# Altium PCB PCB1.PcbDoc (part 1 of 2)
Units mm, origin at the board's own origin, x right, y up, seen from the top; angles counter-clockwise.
Board outline 98.6 x 67.31 mm, 4 copper layers (Top Layer, GND, PWR, Bottom Layer), stack 1.57 mm thick; 89 components, 101 nets, 372 pads, 350 vias.
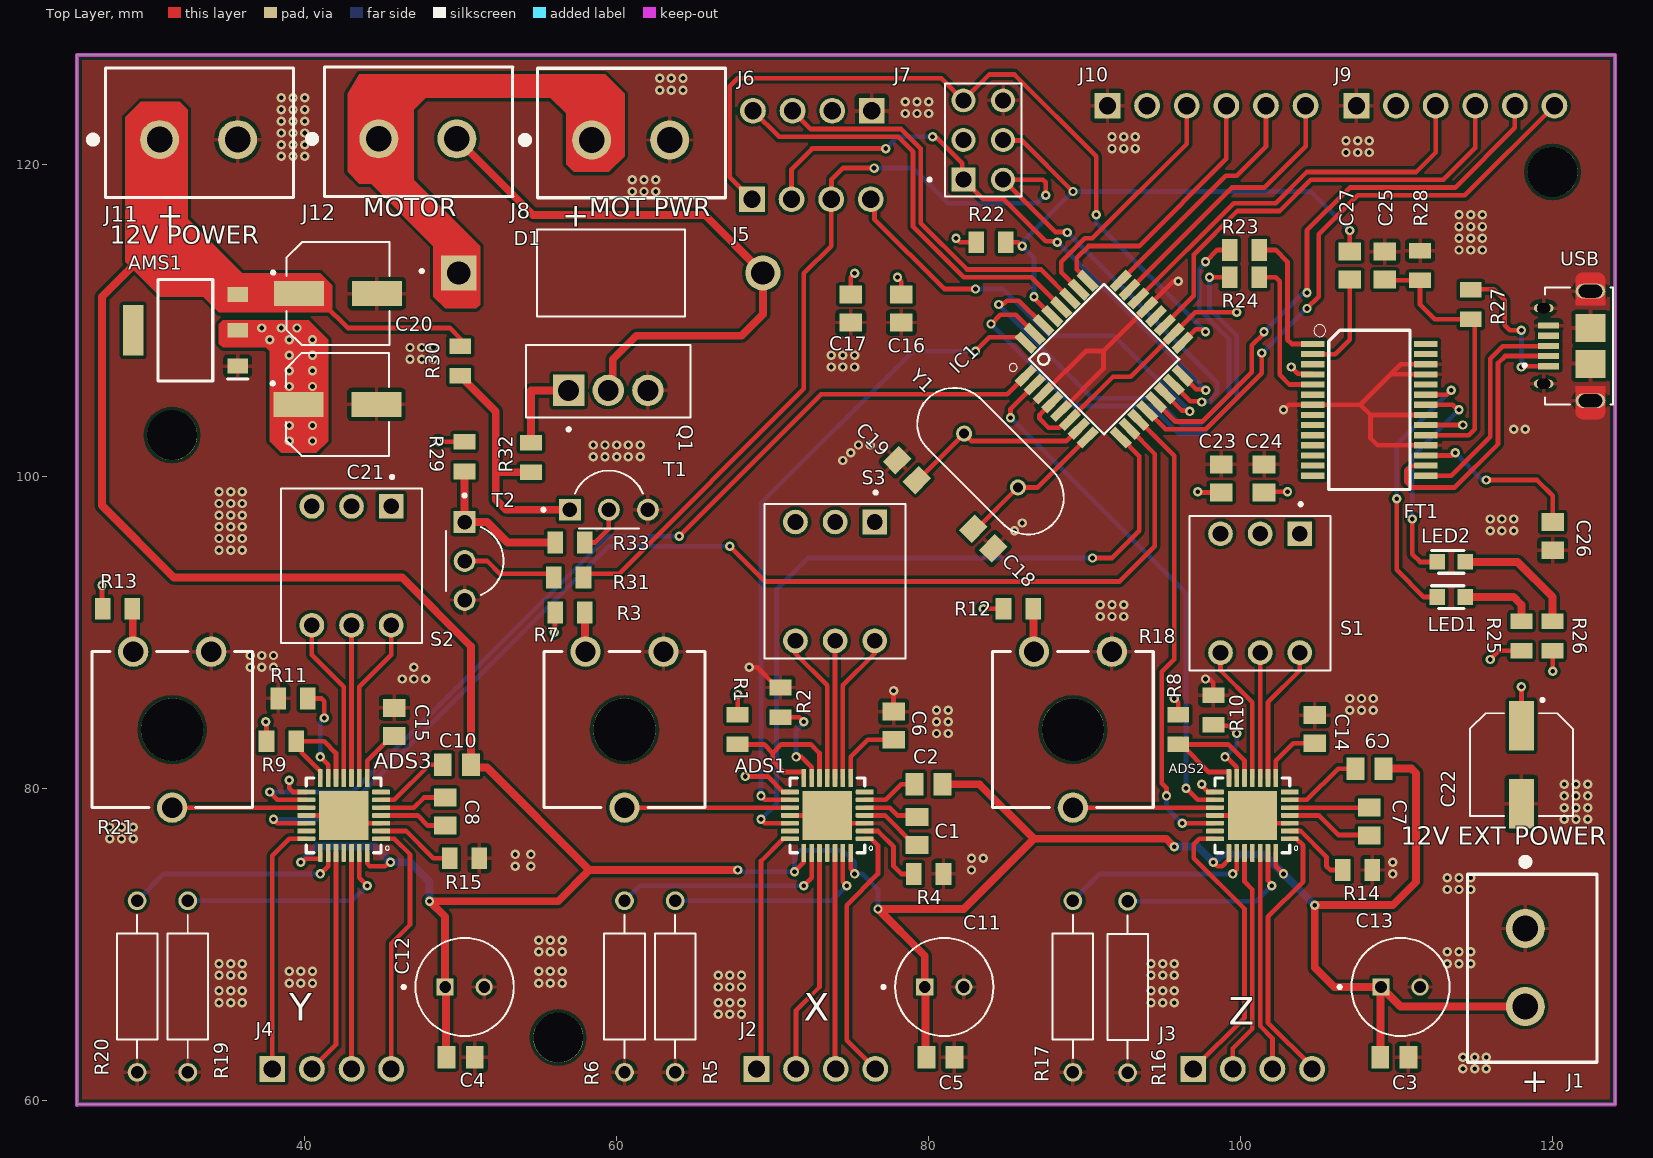
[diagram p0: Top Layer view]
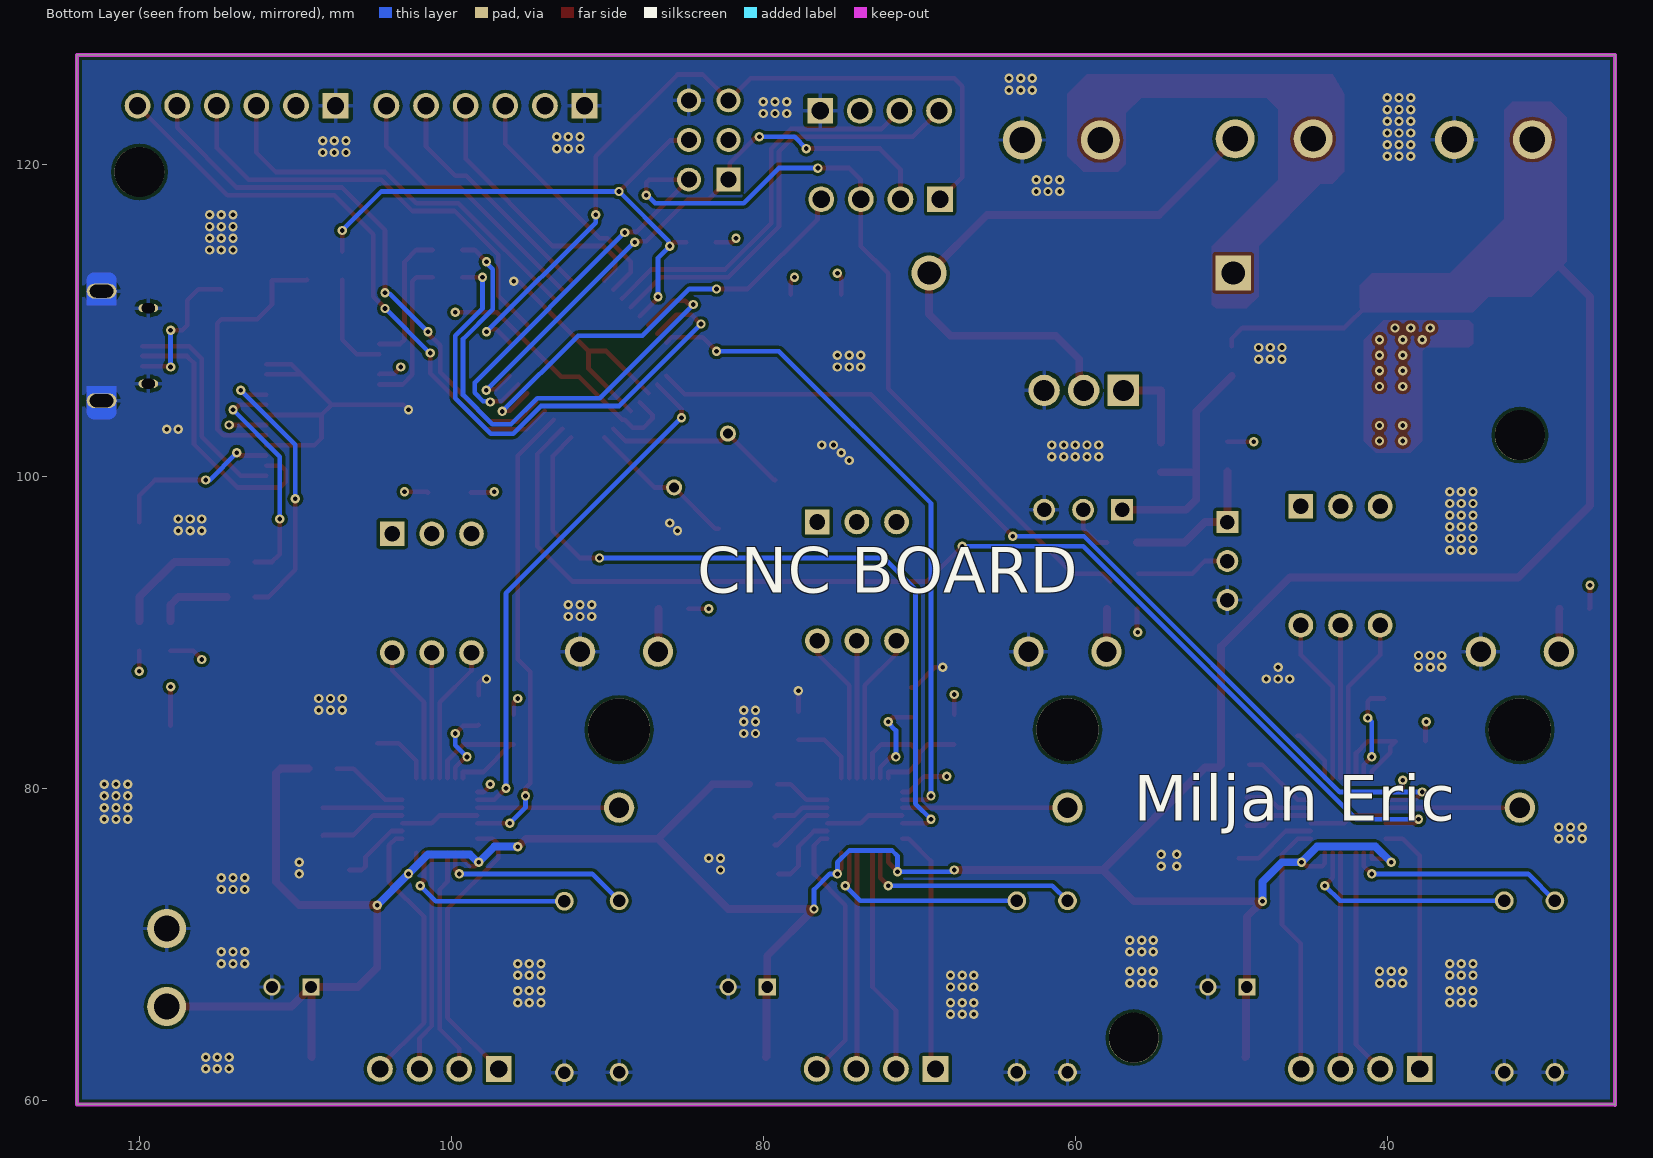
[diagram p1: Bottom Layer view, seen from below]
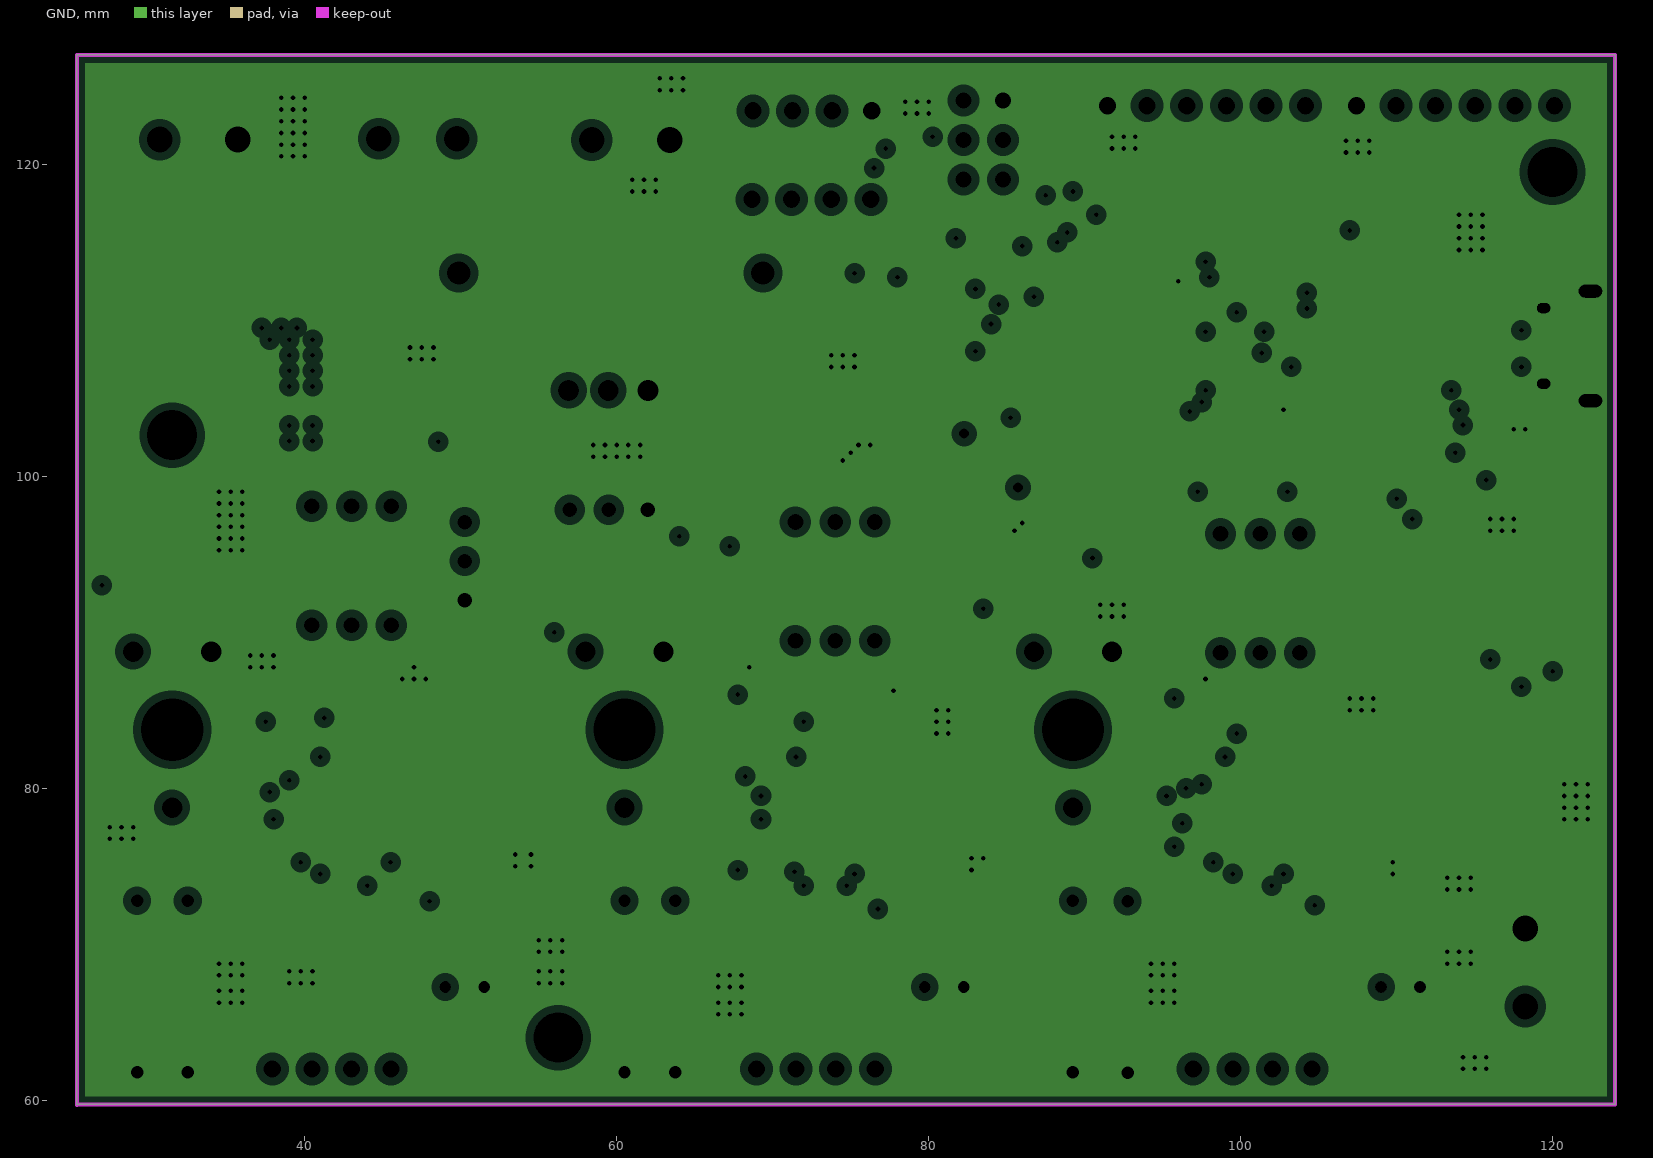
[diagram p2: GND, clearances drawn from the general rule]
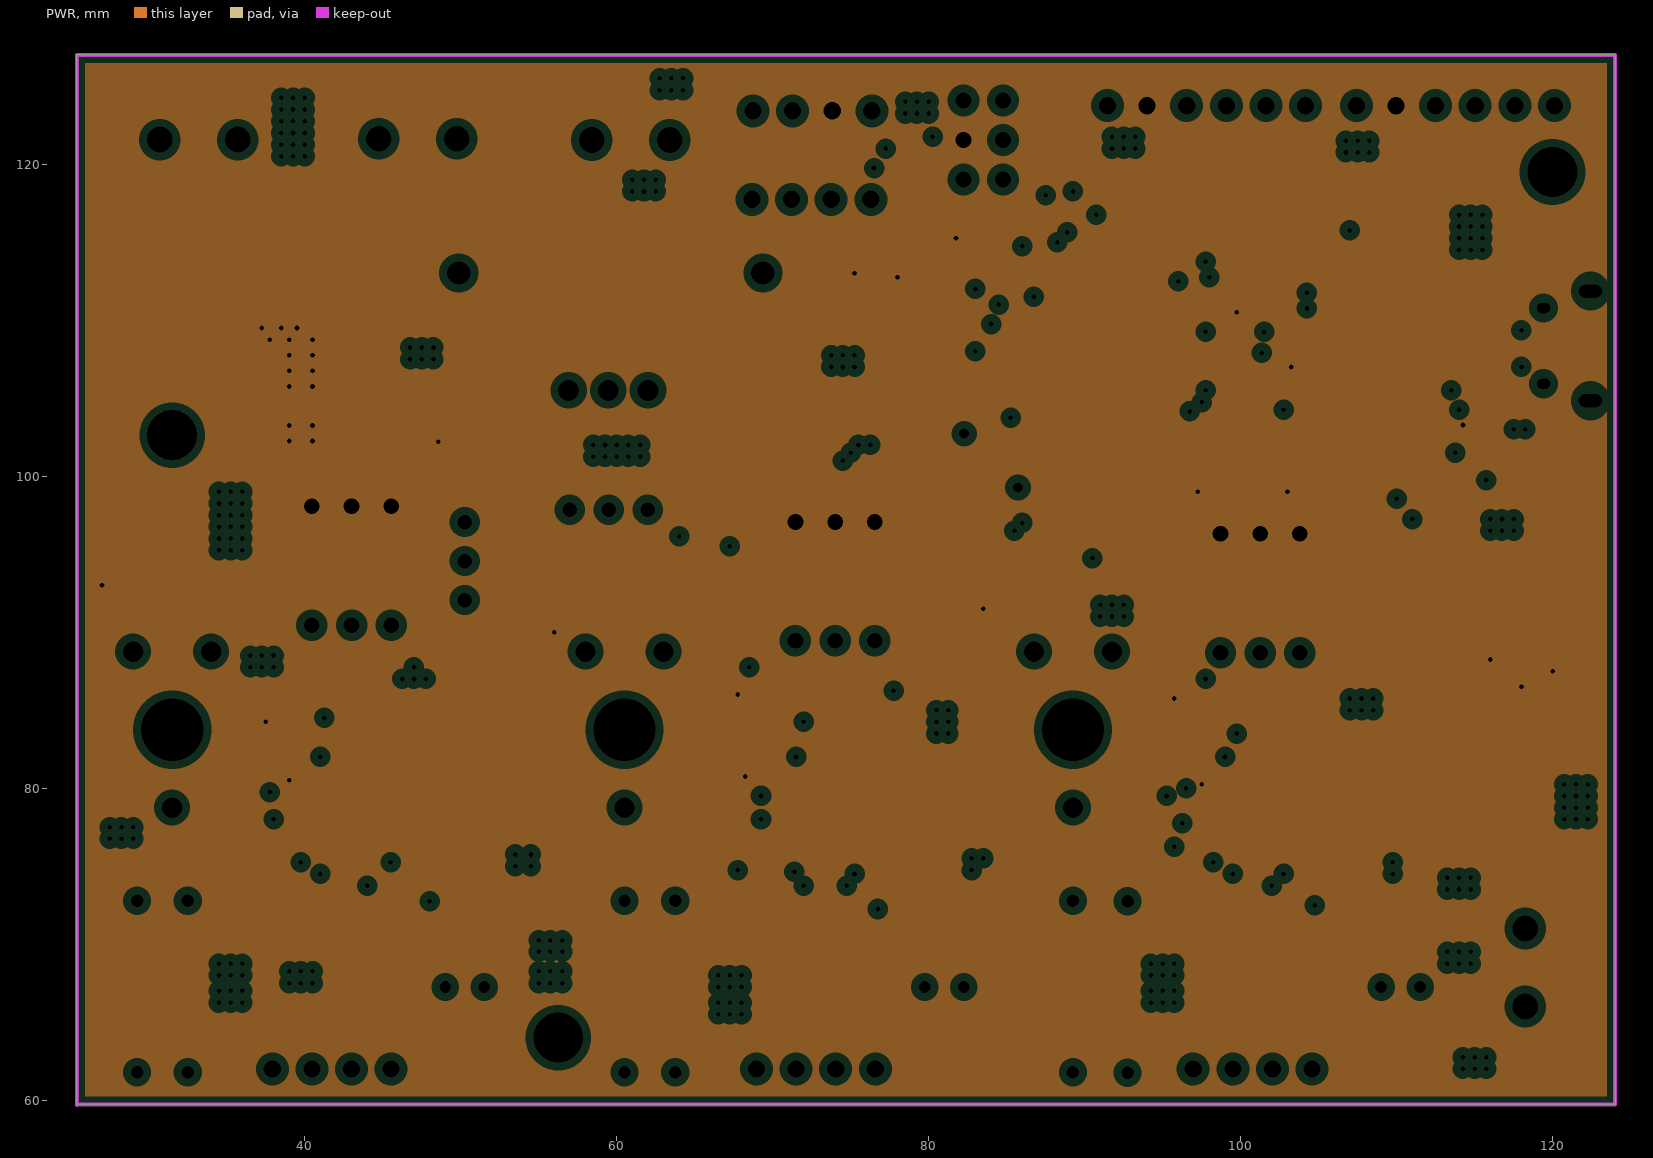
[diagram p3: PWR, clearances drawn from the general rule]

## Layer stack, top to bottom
Top Solder: solder mask 0.0102, Solder Resist, Dk 3.5
Top Layer: signal copper 0.035
Dielectric 2: prepreg 0.2, PP-006, Dk 4.1
GND: plane copper 0.0175, net GND
Dielectric 1: dielectric 1.065, FR-4, Dk 4.8
PWR: plane copper 0.0175, net VCC_5V
Dielectric 3: prepreg 0.2, PP-006, Dk 4.1
Bottom Layer: signal copper 0.035
Bottom Solder: solder mask 0.0102, Solder Resist, Dk 3.5

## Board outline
25.4,59.69 25.431,59.721 124,59.721 124,127 25.4,127

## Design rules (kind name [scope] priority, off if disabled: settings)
Clearance [All] p1: gap=0.2 ignorepadtopadclearanceinfootprint=FALSE
HoleSize [All] p1: absolutevalues=TRUE maxlimit=4 minlimit=0.025 maxpercent=80.000 minpercent=20.000
MinimumSolderMaskSliver [All] p1: minsoldermaskwidth=0.046
PlaneClearance [All] p1: clearance=0.508
PlaneConnect [All] p1: pad.planeconnectstyle=Relief pad.reliefexpansion=0.508 pad.reliefentries=4 pad.reliefconductorwidth=0.254 pad.reliefairgap=0.254 via.planeconnectstyle=Direct via.reliefexpansion=0.508 via.reliefentries=4 via.reliefconductorwidth=0.254 via.reliefairgap=0.254
PolygonConnect [All] p1: thpad.connectstyle=Relief thpad.reliefconductorwidth=0.254 thpad.reliefentries=4 thpad.polygonreliefangle="90 Angle" thpad.airgapwidth=0.254 smdpad.connectstyle=Relief smdpad.reliefconductorwidth=0.254 smdpad.reliefentries=4 smdpad.polygonreliefangle="90 Angle" smdpad.airgapwidth=0.254 via.connectstyle=Direct via.reliefconductorwidth=0.254 via.reliefentries=4 via.polygonreliefangle="90 Angle" via.airgapwidth=0.254
RoutingVias [All] p1: holewidth=0.711 width=1.27 viastyle="Through Hole" minholewidth=0.711 minwidth=1.27 maxholewidth=0.711 maxwidth=1.27
SilkToSilkClearance [All] p1: silktosilkclearance=0.001
SilkToSolderMaskClearance [IsPad] p1: minsilkscreentomaskgap=0.001 clearancetoexposedcopper=TRUE
SolderMaskExpansion [All] p1: expansion=0.102
UnpouredPolygon [All] p1: allowunpoured=TRUE allowshelved=TRUE
Width [All] p1: maxlimit=0.5 minlimit=0.2 preferedwidth=0.3
23 further rules are at their usual default settings.

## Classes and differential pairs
component class U_A4988Driver: ADS1 ADS2 ADS3 C1 C2 C3 C4 C5 C6 C7 C8 C9 C10 C11 C12 C13 C14 C15 J1 J2 J3 J4 R1 R2 R3 R4 R5 R6 R7 R8 R9 R10 R11 R12 R13 R14 R15 R16 R17 R18 R19 R20 R21 S1 S2 S3
component class U_ATMega328-AU: C16 C17 C18 C19 IC1 J5 J6 J7 J8 J9 J10 R22 R23 R24 Y1
component class U_FT232RL: C22 C23 C24 C25 C26 C27 FT1 LED1 LED2 R25 R26 R27 R28 USB
component class U_IRF540MotorControl: D1 J12 Q1 R29 R30 R31 R32 R33 T1 T2
component class U_PowerSchematics: AMS1 C20 C21 J11

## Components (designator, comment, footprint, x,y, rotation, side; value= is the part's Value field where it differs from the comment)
ADS1 "A4982" QFN50P500X500X90-29N 73.5,78.25 r180 top
ADS2 "A4982" QFN50P500X500X90-29N 100.75,78.25 r180 top
ADS3 "A4982" QFN50P500X500X90-29N 42.5,78.25 r180 top
AMS1 "AMS1117-5.0" SOT229P700X180-4N 32.35,109.35 r180 top
C1 "0.1uF" CAPC2012X140N 79.25,77.25 r270 top
C2 "0.1uF" CAPC2012X140N 80,80.25 r0 top
C3 "4.7uF" CAPC2012X140N 109.85,62.75 r180 top
C4 "0.1uF" CAPC2012X140N 50,62.75 r180 top
C5 "0.1uF" CAPC2012X140N 80.75,62.75 r180 top
C6 "0.22uF" CAPC2012X140N 77.75,84 r270 top
C7 "0.1uF" CAPC2012X140N 108.25,77.85 r270 top
C8 "0.1uF" CAPC2012X140N 49,78.5 r270 top
C9 "0.1uF" CAPC2012X140N 108.25,81.25 r0 top
C10 "0.1uF" CAPC2012X140N 49.75,81.5 r0 top
C11 "Cap Pol1" CAPPRD250W50D630H1500 81,67.25 r0 top value=100uF
C12 "Cap Pol1" CAPPRD250W50D630H1500 50.25,67.25 r0 top value=100uF
C13 "Cap Pol1" CAPPRD250W50D630H1500 110.25,67.25 r0 top value=100uF
C14 "0.22uF" CAPC2012X140N 104.75,83.775 r270 top
C15 "0.22uF" CAPC2012X140N 45.75,84.25 r270 top
C16 "100nF" CAPC2012X140N 78.25,110.75 r90 top
C17 "100nF" CAPC2012X140N 75,110.75 r90 top
C18 "22pF" CAPC2012X140N 83.5,96 r315 top
C19 "22pF" CAPC2012X140N 78.614,100.386 r135 top
C20 "10uF" CAP_EEE1CA101WAP 42.125,111.7 r0 top
C21 "10uF" CAP_EEE1CA101WAP 42.1,104.6 r0 top
C22 "10uF" CAP_EEE1CA101WAP 118,81.5 r270 top
C23 "100nF" CAPC2012X140N 98.75,99.85 r270 top
C24 "10nF" CAPC2012X140N 101.5,99.85 r270 top
C25 "100nF" CAPC2012X140N 109.25,113.5 r270 top
C26 "100nF" CAPC2012X140N 120,96.15 r90 top
C27 "100nF" CAPC2012X140N 107,113.5 r90 top
D1 "B550C-13-F" DIOAD1950W125L950D560 59.625,113.025 r0 top
FT1 "FT232RL" SSOP28-0.65-10.2X5.2MM 108.25,104.25 r270 top
IC1 "ATMEGA328-AU" QFP80P900X900X120-32N 91.25,107.5 r45 top
J1 "DB2EVC-3.5-2P-GN" 5MM_2POS_TERM_BLOCK 118.25,71 r270 top
J2 "2.54mm" HEADER1X4 68.96,62 r0 top
J3 "2.54mm" HEADER1X4 96.96,62 r0 top
J4 "2.54mm" HEADER1X4 37.92,62 r0 top
J5 "2.54mm" HEADER1X4 68.67,117.75 r0 top
J6 "2.54mm" HEADER1X4 76.355,123.425 r180 top
J7 "2.54mm" TE_5-146257-3 83.5,121.55 r90 top
J8 "DB2EVC-3.5-2P-GN" 5MM_2POS_TERM_BLOCK 58.4,121.55 r0 top
J9 "2.54mm" HEADER1X6 107.42,123.75 r0 top
J10 "2.54mm" HEADER1X6 91.464,123.75 r0 top
J11 "DB2EVC-3.5-2P-GN" 5MM_2POS_TERM_BLOCK 30.7,121.575 r0 top
J12 "DB2EVC-3.5-2P-GN" 5MM_2POS_TERM_BLOCK 44.75,121.625 r0 top
LED1 "LED-RED" LEDM168X65N_RED 113.5,92.25 r0 top
LED2 "LED-GREEN" LEDM168X65N_GREEN 113.5,94.5 r0 top
Q1 "IRF540NSTRLPBF" TO254P1052X465X1989-3 56.92,105.5 r0 top
R1 "100K" RESC2012X60N 67.75,83.75 r90 top
R2 "10K" RESC2012X60N 70.5,85.5 r270 top
R3 "10K" RESC2012X60N 57,91.25 r180 top
R4 "100K" RESC2012X60N 80,74.5 r180 top
R5 "0.1R" RESAD1100W55L680D260 63.75,67.278 r90 top
R6 "0.1R" RESAD1100W55L680D260 60.5,67.278 r90 top
R7 "RPot" PT10RV10103A2020PMS 63,88.75 r180 top value=5K
R8 "100K" RESC2012X60N 96,83.75 r90 top
R9 "100K" RESC2012X60N 38.5,83 r180 top
R10 "10K" RESC2012X60N 98.25,85 r270 top
R11 "10K" RESC2012X60N 39.25,85.75 r0 top
R12 "10K" RESC2012X60N 85.75,91.5 r180 top
R13 "10K" RESC2012X60N 28,91.5 r180 top
R14 "100K" RESC2012X60N 107.5,74.75 r180 top
R15 "100K" RESC2012X60N 50.25,75.5 r180 top
R16 "0.1R" RESAD1100W55L680D260 92.75,67.25 r90 top
R17 "0.1R" RESAD1100W55L680D260 89.25,67.278 r90 top
R18 "RPot" PT10RV10103A2020PMS 91.75,88.75 r180 top value=5K
R19 "0.1R" RESAD1100W55L680D260 32.5,67.278 r90 top
R20 "0.1R" RESAD1100W55L680D260 29.25,67.278 r90 top
R21 "RPot" PT10RV10103A2020PMS 34,88.75 r180 top value=5K
R22 "10K" RESC2012X60N 84,115 r180 top
R23 "1K" RESC2012X60N 100.25,114.5 r0 top
R24 "1K" RESC2012X60N 100.25,112.75 r0 top
R25 "330R" RESC2012X60N 118,89.75 r270 top
R26 "330R" RESC2012X60N 120,89.75 r270 top
R27 "4K7" RESC2012X60N 114.75,111 r90 top
R28 "10K" RESC2012X60N 111.5,113.5 r270 top
R29 "4K7" RESC2012X60N 50.25,101.25 r90 top
R30 "10K" RESC2012X60N 49.975,107.375 r90 top
R31 "470R" RESC2012X60N 56.92,93.5 r180 top
R32 "470R" RESC2012X60N 54.5,101.2 r90 top
R33 "470R" RESC2012X60N 57,95.75 r0 top
S1 "DS04-254-2-03BK-SMT" SW_DS01-254-S-03BE 101.25,92.5 r180 top
S2 "DS04-254-2-03BK-SMT" SW_DS01-254-S-03BE 43,94.25 r180 top
S3 "DS04-254-2-03BK-SMT" SW_DS01-254-S-03BE 74,93.25 r180 top
T1 "BC547" TO92250P510H770-3 59.5,98.5 r0 top
T2 "BC547" TO92250P510H770-3 50.905,94.56 r270 top
USB "ZX62D-B-5P8" HRS_ZX62D-B-5P8 122.35,108.35 r90 top
Y1 "ABL-16.000MHZ" XTAL_ECS-30-S-1X 84,101 r315 top

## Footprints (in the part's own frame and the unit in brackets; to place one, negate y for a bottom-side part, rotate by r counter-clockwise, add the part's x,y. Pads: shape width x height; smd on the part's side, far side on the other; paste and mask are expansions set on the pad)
5MM_2POS_TERM_BLOCK [mm]
  round 2.5 hole 1.65: 1(0,0) 2(5,0)
  silkscreen extent -4.47,-3.7 8.58,4.6, body extent -2.54,-2.9 7.62,4.35, height 9.68
CAP_EEE1CA101WAP [mm]
  rect 3.2x1.6 smd: 1(-2.5,0) 2(2.5,0)
  silkscreen extent -4.25,-3.3 3.3,3.3, body extent -3.65,-3.3 3.65,3.3, height 5.8
CAPC2012X140N [mm]
  rect 1.15x1.45 smd: 1(-0.9,0) 2(0.9,0)
  body extent -1,-0.63 1,0.63, height 0.94
CAPPRD250W50D630H1500 [mm]
  rect 1.1x1.1 / inner round 1.1 / far side rect 1.1x1.1 hole 0.75: 1(-1.25,0)
  round 1.1 hole 0.75: 2(1.25,0)
  silkscreen extent -4,-3.15 3.15,3.15, body extent -3.15,-3.15 3.15,3.15, height 15
DIOAD1950W125L950D560 [mm]
  rect 2.25x2.25 hole 1.5: 1(-9.75,0)
  round 2.25 hole 1.5: 2(9.75,0)
  silkscreen extent -12.22,-2.8 4.75,2.8, body extent -10.38,-2.65 10.78,2.65, height 5.3
HEADER1X4 [mm]
  rect 1.65x1.65 hole 1.1: 1(0,0)
  round 1.65 hole 1.1: 2(2.54,0) 3(5.08,0) 4(7.62,0)
  body extent -1.27,-1.27 8.89,1.27, height 8.7
HEADER1X6 [mm]
  rect 1.65x1.65 hole 1.1: 1(0,0)
  round 1.65 hole 1.1: 2(2.54,0) 3(5.08,0) 4(7.62,0) 5(10.16,0) 6(12.7,0)
  body extent -1.19,-1.22 13.89,1.22, height 8.7
HRS_ZX62D-B-5P8 [mm]
  rect 0.4x1.35 smd mask+0.1: 1(-1.3,2.6) 2(-0.65,2.6) 3(0,2.6) 4(0.65,2.6) 5(1.3,2.6)
  oval 0.525x1.25 hole 0.65 slot 0.85 at 90 deg mask+0.1: S1(-2.425,2.925) S2(2.425,2.925)
  oval 0.95x1.9 hole 0.825 slot 1.5 at 90 deg mask+0.1: S3(-3.512,-0.075) S6(3.512,-0.075)
  rect 1.8x1.9 smd mask+0.1: S4(-1.15,-0.075) S5(1.15,-0.075)
  Top Layer region: 4.226,0.874 4.252,0.872 4.278,0.869 4.304,0.864 4.329,0.858 4.355,0.851 4.379,0.842 4.403,0.832 4.427,0.821 4.45,0.808 4.472,0.794 4.494,0.78 4.515,0.764 4.535,0.747 4.554,0.729 4.572,0.71 4.589,0.69 4.605,0.669 4.619,0.647 4.633,0.625 4.646,0.602 4.657,0.578 4.667,0.554 4.676,0.53 4.683,0.504 4.689,0.479 4.694,0.453 4.697,0.427 4.699,0.401 4.7,0.375 4.7,-0.075 3.925,-0.075 3.925,0.4 3.925,0.414 3.923,0.429 3.922,0.443 3.919,0.457 3.916,0.471 3.912,0.485 3.907,0.499 3.901,0.512 3.895,0.525 3.888,0.538 3.881,0.55 3.872,0.562 3.864,0.573 3.854,0.584 3.844,0.594 3.834,0.604 3.823,0.614 3.812,0.622 3.8,0.631 3.787,0.638 3.775,0.645 3.762,0.651 3.749,0.657 3.735,0.662 3.721,0.666 3.707,0.669 3.693,0.672 3.679,0.673 3.664,0.675 3.384,0.675 3.369,0.673 3.353,0.671 3.338,0.668 3.322,0.665 3.307,0.66 3.292,0.655 3.278,0.649 3.264,0.642 3.25,0.635 3.237,0.627 3.224,0.618 3.211,0.608 3.199,0.598 3.188,0.587 3.177,0.576 3.167,0.564 3.157,0.551 3.148,0.538 3.14,0.525 3.133,0.511 3.126,0.497 3.12,0.483 3.115,0.468 3.11,0.453 3.107,0.437 3.104,0.422 3.102,0.406 3.1,0.391 3.1,0.375 3.1,-0.075 2.6,-0.075 2.6,0.875 4.2,0.875
  Top Layer region: -2.6,-1.025 -4.2,-1.025 -4.226,-1.024 -4.252,-1.022 -4.278,-1.019 -4.304,-1.014 -4.329,-1.008 -4.355,-1.001 -4.379,-0.992 -4.403,-0.982 -4.427,-0.971 -4.45,-0.958 -4.472,-0.944 -4.494,-0.93 -4.515,-0.914 -4.535,-0.897 -4.554,-0.879 -4.572,-0.86 -4.589,-0.84 -4.605,-0.819 -4.619,-0.797 -4.633,-0.775 -4.646,-0.752 -4.657,-0.728 -4.667,-0.704 -4.676,-0.68 -4.683,-0.654 -4.689,-0.629 -4.694,-0.603 -4.697,-0.577 -4.699,-0.551 -4.7,-0.525 -4.7,-0.075 -3.925,-0.075 -3.925,-0.55 -3.925,-0.564 -3.923,-0.579 -3.922,-0.593 -3.919,-0.607 -3.916,-0.621 -3.912,-0.635 -3.907,-0.649 -3.901,-0.662 -3.895,-0.675 -3.888,-0.688 -3.881,-0.7 -3.872,-0.712 -3.864,-0.723 -3.854,-0.734 -3.844,-0.744 -3.834,-0.754 -3.823,-0.764 -3.812,-0.772 -3.8,-0.781 -3.787,-0.788 -3.775,-0.795 -3.762,-0.801 -3.749,-0.807 -3.735,-0.812 -3.721,-0.816 -3.707,-0.819 -3.693,-0.822 -3.679,-0.823 -3.664,-0.825 -3.384,-0.825 -3.369,-0.823 -3.353,-0.821 -3.338,-0.818 -3.322,-0.815 -3.307,-0.81 -3.292,-0.805 -3.278,-0.799 -3.264,-0.792 -3.25,-0.785 -3.237,-0.777 -3.224,-0.768 -3.211,-0.758 -3.199,-0.748 -3.188,-0.737 -3.177,-0.726 -3.167,-0.714 -3.157,-0.701 -3.148,-0.688 -3.14,-0.675 -3.133,-0.661 -3.126,-0.647 -3.12,-0.633 -3.115,-0.618 -3.11,-0.603 -3.107,-0.587 -3.104,-0.572 -3.102,-0.556 -3.1,-0.541 -3.1,-0.525 -3.1,-0.075 -2.6,-0.075
  Top Layer region: 4.7,-0.525 4.699,-0.551 4.697,-0.577 4.694,-0.603 4.689,-0.629 4.683,-0.654 4.676,-0.68 4.667,-0.704 4.657,-0.728 4.646,-0.752 4.633,-0.775 4.619,-0.797 4.605,-0.819 4.589,-0.84 4.572,-0.86 4.554,-0.879 4.535,-0.897 4.515,-0.914 4.494,-0.93 4.472,-0.944 4.45,-0.958 4.427,-0.971 4.403,-0.982 4.379,-0.992 4.355,-1.001 4.329,-1.008 4.304,-1.014 4.278,-1.019 4.252,-1.022 4.226,-1.024 4.2,-1.025 2.6,-1.025 2.6,-0.075 3.1,-0.075 3.1,-0.525 3.1,-0.541 3.102,-0.556 3.104,-0.572 3.107,-0.587 3.11,-0.603 3.115,-0.618 3.12,-0.633 3.126,-0.647 3.133,-0.661 3.14,-0.675 3.148,-0.688 3.157,-0.701 3.167,-0.714 3.177,-0.726 3.188,-0.737 3.199,-0.748 3.211,-0.758 3.224,-0.768 3.237,-0.777 3.25,-0.785 3.264,-0.792 3.278,-0.799 3.292,-0.805 3.307,-0.81 3.322,-0.815 3.338,-0.818 3.353,-0.821 3.369,-0.823 3.384,-0.825 3.641,-0.825 3.656,-0.823 3.672,-0.821 3.687,-0.818 3.703,-0.815 3.718,-0.81 3.733,-0.805 3.747,-0.799 3.761,-0.792 3.775,-0.785 3.788,-0.777 3.801,-0.768 3.814,-0.758 3.826,-0.748 3.837,-0.737 3.848,-0.726 3.858,-0.714 3.868,-0.701 3.877,-0.688 3.885,-0.675 3.892,-0.661 3.899,-0.647 3.905,-0.633 3.91,-0.618 3.915,-0.603 3.918,-0.587 3.921,-0.572 3.923,-0.556 3.925,-0.541 3.925,-0.525 3.925,-0.075 4.7,-0.075
  Top Layer region: -2.6,-0.075 -3.1,-0.075 -3.1,0.375 -3.1,0.391 -3.102,0.406 -3.104,0.422 -3.107,0.437 -3.11,0.453 -3.115,0.468 -3.12,0.483 -3.126,0.497 -3.133,0.511 -3.14,0.525 -3.148,0.538 -3.157,0.551 -3.167,0.564 -3.177,0.576 -3.188,0.587 -3.199,0.598 -3.211,0.608 -3.224,0.618 -3.237,0.627 -3.25,0.635 -3.264,0.642 -3.278,0.649 -3.292,0.655 -3.307,0.66 -3.322,0.665 -3.338,0.668 -3.353,0.671 -3.369,0.673 -3.384,0.675 -3.641,0.675 -3.656,0.673 -3.672,0.671 -3.687,0.668 -3.703,0.665 -3.718,0.66 -3.733,0.655 -3.747,0.649 -3.761,0.642 -3.775,0.635 -3.788,0.627 -3.801,0.618 -3.814,0.608 -3.826,0.598 -3.837,0.587 -3.848,0.576 -3.858,0.564 -3.868,0.551 -3.877,0.538 -3.885,0.525 -3.892,0.511 -3.899,0.497 -3.905,0.483 -3.91,0.468 -3.915,0.453 -3.918,0.437 -3.921,0.422 -3.923,0.406 -3.925,0.391 -3.925,0.375 -3.925,-0.075 -4.7,-0.075 -4.7,0.375 -4.699,0.401 -4.697,0.427 -4.694,0.453 -4.689,0.479 -4.683,0.504 -4.676,0.53 -4.667,0.554 -4.657,0.578 -4.646,0.602 -4.633,0.625 -4.619,0.647 -4.605,0.669 -4.589,0.69 -4.572,0.71 -4.554,0.729 -4.535,0.747 -4.515,0.764 -4.494,0.78 -4.472,0.794 -4.45,0.808 -4.427,0.821 -4.403,0.832 -4.379,0.842 -4.355,0.851 -4.329,0.858 -4.304,0.864 -4.278,0.869 -4.252,0.872 -4.226,0.874 -4.2,0.875 -2.6,0.875
  Bottom Layer region: 4.226,0.874 4.252,0.872 4.278,0.869 4.304,0.864 4.329,0.858 4.355,0.851 4.379,0.842 4.403,0.832 4.427,0.821 4.45,0.808 4.472,0.794 4.494,0.78 4.515,0.764 4.535,0.747 4.554,0.729 4.572,0.71 4.589,0.69 4.605,0.669 4.619,0.647 4.633,0.625 4.646,0.602 4.657,0.578 4.667,0.554 4.676,0.53 4.683,0.504 4.689,0.479 4.694,0.453 4.697,0.427 4.699,0.401 4.7,0.375 4.7,-0.075 3.925,-0.075 3.925,0.4 3.925,0.414 3.923,0.429 3.922,0.443 3.919,0.457 3.916,0.471 3.912,0.485 3.907,0.499 3.901,0.512 3.895,0.525 3.888,0.538 3.881,0.55 3.872,0.562 3.864,0.573 3.854,0.584 3.844,0.594 3.834,0.604 3.823,0.614 3.812,0.622 3.8,0.631 3.787,0.638 3.775,0.645 3.762,0.651 3.749,0.657 3.735,0.662 3.721,0.666 3.707,0.669 3.693,0.672 3.679,0.673 3.664,0.675 3.384,0.675 3.369,0.673 3.353,0.671 3.338,0.668 3.322,0.665 3.307,0.66 3.292,0.655 3.278,0.649 3.264,0.642 3.25,0.635 3.237,0.627 3.224,0.618 3.211,0.608 3.199,0.598 3.188,0.587 3.177,0.576 3.167,0.564 3.157,0.551 3.148,0.538 3.14,0.525 3.133,0.511 3.126,0.497 3.12,0.483 3.115,0.468 3.11,0.453 3.107,0.437 3.104,0.422 3.102,0.406 3.1,0.391 3.1,0.375 3.1,-0.075 2.6,-0.075 2.6,0.875 4.2,0.875
  Bottom Layer region: -2.6,-1.025 -4.2,-1.025 -4.226,-1.024 -4.252,-1.022 -4.278,-1.019 -4.304,-1.014 -4.329,-1.008 -4.355,-1.001 -4.379,-0.992 -4.403,-0.982 -4.427,-0.971 -4.45,-0.958 -4.472,-0.944 -4.494,-0.93 -4.515,-0.914 -4.535,-0.897 -4.554,-0.879 -4.572,-0.86 -4.589,-0.84 -4.605,-0.819 -4.619,-0.797 -4.633,-0.775 -4.646,-0.752 -4.657,-0.728 -4.667,-0.704 -4.676,-0.68 -4.683,-0.654 -4.689,-0.629 -4.694,-0.603 -4.697,-0.577 -4.699,-0.551 -4.7,-0.525 -4.7,-0.075 -3.925,-0.075 -3.925,-0.55 -3.925,-0.564 -3.923,-0.579 -3.922,-0.593 -3.919,-0.607 -3.916,-0.621 -3.912,-0.635 -3.907,-0.649 -3.901,-0.662 -3.895,-0.675 -3.888,-0.688 -3.881,-0.7 -3.872,-0.712 -3.864,-0.723 -3.854,-0.734 -3.844,-0.744 -3.834,-0.754 -3.823,-0.764 -3.812,-0.772 -3.8,-0.781 -3.787,-0.788 -3.775,-0.795 -3.762,-0.801 -3.749,-0.807 -3.735,-0.812 -3.721,-0.816 -3.707,-0.819 -3.693,-0.822 -3.679,-0.823 -3.664,-0.825 -3.384,-0.825 -3.369,-0.823 -3.353,-0.821 -3.338,-0.818 -3.322,-0.815 -3.307,-0.81 -3.292,-0.805 -3.278,-0.799 -3.264,-0.792 -3.25,-0.785 -3.237,-0.777 -3.224,-0.768 -3.211,-0.758 -3.199,-0.748 -3.188,-0.737 -3.177,-0.726 -3.167,-0.714 -3.157,-0.701 -3.148,-0.688 -3.14,-0.675 -3.133,-0.661 -3.126,-0.647 -3.12,-0.633 -3.115,-0.618 -3.11,-0.603 -3.107,-0.587 -3.104,-0.572 -3.102,-0.556 -3.1,-0.541 -3.1,-0.525 -3.1,-0.075 -2.6,-0.075
  Bottom Layer region: 4.7,-0.525 4.699,-0.551 4.697,-0.577 4.694,-0.603 4.689,-0.629 4.683,-0.654 4.676,-0.68 4.667,-0.704 4.657,-0.728 4.646,-0.752 4.633,-0.775 4.619,-0.797 4.605,-0.819 4.589,-0.84 4.572,-0.86 4.554,-0.879 4.535,-0.897 4.515,-0.914 4.494,-0.93 4.472,-0.944 4.45,-0.958 4.427,-0.971 4.403,-0.982 4.379,-0.992 4.355,-1.001 4.329,-1.008 4.304,-1.014 4.278,-1.019 4.252,-1.022 4.226,-1.024 4.2,-1.025 2.6,-1.025 2.6,-0.075 3.1,-0.075 3.1,-0.525 3.1,-0.541 3.102,-0.556 3.104,-0.572 3.107,-0.587 3.11,-0.603 3.115,-0.618 3.12,-0.633 3.126,-0.647 3.133,-0.661 3.14,-0.675 3.148,-0.688 3.157,-0.701 3.167,-0.714 3.177,-0.726 3.188,-0.737 3.199,-0.748 3.211,-0.758 3.224,-0.768 3.237,-0.777 3.25,-0.785 3.264,-0.792 3.278,-0.799 3.292,-0.805 3.307,-0.81 3.322,-0.815 3.338,-0.818 3.353,-0.821 3.369,-0.823 3.384,-0.825 3.641,-0.825 3.656,-0.823 3.672,-0.821 3.687,-0.818 3.703,-0.815 3.718,-0.81 3.733,-0.805 3.747,-0.799 3.761,-0.792 3.775,-0.785 3.788,-0.777 3.801,-0.768 3.814,-0.758 3.826,-0.748 3.837,-0.737 3.848,-0.726 3.858,-0.714 3.868,-0.701 3.877,-0.688 3.885,-0.675 3.892,-0.661 3.899,-0.647 3.905,-0.633 3.91,-0.618 3.915,-0.603 3.918,-0.587 3.921,-0.572 3.923,-0.556 3.925,-0.541 3.925,-0.525 3.925,-0.075 4.7,-0.075
  Bottom Layer region: -2.6,-0.075 -3.1,-0.075 -3.1,0.375 -3.1,0.391 -3.102,0.406 -3.104,0.422 -3.107,0.437 -3.11,0.453 -3.115,0.468 -3.12,0.483 -3.126,0.497 -3.133,0.511 -3.14,0.525 -3.148,0.538 -3.157,0.551 -3.167,0.564 -3.177,0.576 -3.188,0.587 -3.199,0.598 -3.211,0.608 -3.224,0.618 -3.237,0.627 -3.25,0.635 -3.264,0.642 -3.278,0.649 -3.292,0.655 -3.307,0.66 -3.322,0.665 -3.338,0.668 -3.353,0.671 -3.369,0.673 -3.384,0.675 -3.641,0.675 -3.656,0.673 -3.672,0.671 -3.687,0.668 -3.703,0.665 -3.718,0.66 -3.733,0.655 -3.747,0.649 -3.761,0.642 -3.775,0.635 -3.788,0.627 -3.801,0.618 -3.814,0.608 -3.826,0.598 -3.837,0.587 -3.848,0.576 -3.858,0.564 -3.868,0.551 -3.877,0.538 -3.885,0.525 -3.892,0.511 -3.899,0.497 -3.905,0.483 -3.91,0.468 -3.915,0.453 -3.918,0.437 -3.921,0.422 -3.923,0.406 -3.925,0.391 -3.925,0.375 -3.925,-0.075 -4.7,-0.075 -4.7,0.375 -4.699,0.401 -4.697,0.427 -4.694,0.453 -4.689,0.479 -4.683,0.504 -4.676,0.53 -4.667,0.554 -4.657,0.578 -4.646,0.602 -4.633,0.625 -4.619,0.647 -4.605,0.669 -4.589,0.69 -4.572,0.71 -4.554,0.729 -4.535,0.747 -4.515,0.764 -4.494,0.78 -4.472,0.794 -4.45,0.808 -4.427,0.821 -4.403,0.832 -4.379,0.842 -4.355,0.851 -4.329,0.858 -4.304,0.864 -4.278,0.869 -4.252,0.872 -4.226,0.874 -4.2,0.875 -2.6,0.875
  silkscreen extent -3.75,-1.53 3.75,4.24, body extent -4.05,-2.95 4.05,2.85, height 1.48
LEDM168X65N_GREEN [mm]
  rect 1x1 smd: 1(-0.9,0) 2(0.9,0)
  silkscreen extent -1.25,-0.72 0.8,0.72, body extent -0.8,-0.4 0.8,0.4, height 0.6
LEDM168X65N_RED [mm]
  rect 1x1 smd: 1(-0.9,0) 2(0.9,0)
  silkscreen extent -1.25,-0.72 0.8,0.72, body extent -0.8,-0.4 0.8,0.4, height 0.6
PT10RV10103A2020PMS [mm]
  round 1.95 hole 1.3: 1(0,0) 2(5,0) 3(2.5,10)
  round 4 hole 4 unplated: ""(2.5,5)
  silkscreen extent -2.65,0 7.65,10, body extent -1.6,-1.03 7.4,10.77, height 6.86
QFN50P500X500X90-29N [mm]
  rrect30% 1.15x0.3 smd mask+0: 1(-2.4,1.5) 2(-2.4,1) 3(-2.4,0.5) 4(-2.4,0) 5(-2.4,-0.5) 6(-2.4,-1) 7(-2.4,-1.5) 15(2.4,-1.5) 16(2.4,-1) 17(2.4,-0.5) 18(2.4,0) 19(2.4,0.5) 20(2.4,1) 21(2.4,1.5)
  rrect30% 0.3x1.15 smd mask+0: 8(-1.5,-2.4) 9(-1,-2.4) 10(-0.5,-2.4) 11(0,-2.4) 12(0.5,-2.4) 13(1,-2.4) 14(1.5,-2.4) 22(1.5,2.4) 23(1,2.4) 24(0.5,2.4) 25(0,2.4) 26(-0.5,2.4) 27(-1,2.4) 28(-1.5,2.4)
  rect 3.15x3.15 smd paste-3: 29(0,0)
  silkscreen extent -2.93,-2.4 2.4,2.4, body extent -2.42,-2.5 2.58,2.5, height 1
QFP80P900X900X120-32N [mm]
  rect 1.5x0.55 smd: 1(-4.3,2.8) 2(-4.3,2) 3(-4.3,1.2) 4(-4.3,0.4) 5(-4.3,-0.4) 6(-4.3,-1.2) 7(-4.3,-2) 8(-4.3,-2.8) 17(4.3,-2.8) 18(4.3,-2) 19(4.3,-1.2) 20(4.3,-0.4) 21(4.3,0.4) 22(4.3,1.2) 23(4.3,2) 24(4.3,2.8)
  rect 0.55x1.5 smd: 9(-2.8,-4.3) 10(-2,-4.3) 11(-1.2,-4.3) 12(-0.4,-4.3) 13(0.4,-4.3) 14(1.2,-4.3) 15(2,-4.3) 16(2.8,-4.3) 25(2.8,4.3) 26(2,4.3) 27(1.2,4.3) 28(0.4,4.3) 29(-0.4,4.3) 30(-1.2,4.3) 31(-2,4.3) 32(-2.8,4.3)
  silkscreen extent -4.75,-3.4 3.4,4, body extent -4.5,-4.5 4.5,4.5, height 0.53
RESAD1100W55L680D260 [mm]
  round 1.2 hole 0.8: 1(-5.5,0) 2(5.5,0)
  silkscreen extent -4.58,-1.3 4.58,1.3, body extent -5.77,-1.3 5.77,1.3, height 2.6
RESC2012X60N [mm]
  rect 1x1.4 smd: 1(-0.95,0) 2(0.95,0)
  body extent -1,-0.63 1,0.63, height 0.6
SOT229P700X180-4N [mm]
  rect 1.3x0.95 smd: 1(-3.35,2.29) 2(-3.35,0) 3(-3.35,-2.29)
  rect 1.3x3.25 smd: 4(3.35,0)
  silkscreen extent -4,-3.25 1.75,3.25, body extent -3.5,-3.25 3.5,3.25, height 1.8
SSOP28-0.65-10.2X5.2MM [mm]
  rect 0.4x1.5 smd: 1(-4.225,-3.625) 2(-3.575,-3.625) 3(-2.925,-3.625) 4(-2.275,-3.625) 5(-1.625,-3.625) 6(-0.975,-3.625) 7(-0.325,-3.625) 8(0.325,-3.625) 9(0.975,-3.625) 10(1.625,-3.625) 11(2.275,-3.625) 12(2.925,-3.625) 13(3.575,-3.625) 14(4.225,-3.625) 15(4.225,3.625) 16(3.575,3.625) 17(2.925,3.625) 18(2.275,3.625) 19(1.625,3.625) 20(0.975,3.625) 21(0.325,3.625) 22(-0.325,3.625) 23(-0.975,3.625) 24(-1.625,3.625) 25(-2.275,3.625) 26(-2.925,3.625) 27(-3.575,3.625) 28(-4.225,3.625)
  silkscreen extent -5.46,-3.55 5.1,2.6, body extent -5.1,-3.9 5.1,3.9, height 2
SW_DS01-254-S-03BE [mm]
  rect 1.58x1.58 / inner round 1.58 / far side rect 1.58x1.58 hole 1: 1A(-2.54,-3.81)
  round 1.58 hole 1: 1B(-2.54,3.81) 2A(0,-3.81) 2B(0,3.81) 3A(2.54,-3.81) 3B(2.54,3.81)
  silkscreen extent -4.52,-5.8 4.52,4.95, body extent -4.48,-4.92 4.5,4.98, height 7.05
TE_5-146257-3 [mm]
  rect 1.53x1.53 / inner round 1.53 / far side rect 1.53x1.53 hole 1.02: 1(-2.54,1.27)
  round 1.53 hole 1.02: 2(0,1.27) 3(2.54,1.27) 4(-2.54,-1.27) 5(0,-1.27) 6(2.54,-1.27)
  silkscreen extent -3.61,-2.44 3.61,3.54, body extent -3.34,-2.33 3.88,2.55, height 5.33
TO254P1052X465X1989-3 [mm]
  rect 2.01x2.01 hole 1.34: 1(0,0)
  round 2.01 hole 1.34: 2(2.54,0) 3(5.08,0)
  silkscreen extent -2.72,-2.6 7.8,2.91, body extent -2.52,-1.7 7.57,2.75, height 19.84
TO92250P510H770-3 [mm]
  round 1.4 hole 0.93: B(0,-0.655) E(2.5,-0.655)
  rect 1.4x1.4 hole 0.93: C(-2.5,-0.655)
  silkscreen extent -4.3,-1.85 2.18,1.85, body extent -2.38,-1.43 2.38,2.19, height 5.33
XTAL_ECS-30-S-1X [mm]
  round 1.03 hole 0.63: 1(-2.44,0) 2(2.44,0)
  silkscreen extent -5.68,-2.33 5.68,2.33, body extent -5.7,-2.25 5.65,2.4, height 3.5

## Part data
C1 C2 C4 C5 C7 C8 C9 C10: library part "CAP CER 0.1uF", "CAP CER 0.1uF"
C3: library part "CAP CER 4.7uF", "CAP CER 4.7uF"
C6 C14 C15: library part "CAP CER 0.22uF 0603 50VDC 10% X5R", "CAP CER 0.22uF 0603 50VDC 10% X5R", Dielectric=X5R, Manufacturer=YAGEO, Manufacturer Part Number=CC0603JRNPO9BN180, Package=0603, Supplier Part Number 1=603-CC603JRNPO9BN180, Tolerance=10%, Voltage=50V
C11 C12 C13: "Polarized Capacitor (Radial)"
C16 C17 C23 C25 C26 C27: library part "CAP CER 100nF 0603 25VDC 10% X7R", "CAP CER 100nF 0603 25VDC 10% X7R", Dielectric=X7R, Manufacturer="Samsung Electro-Mechanics", Manufacturer Part Number=CL10B104KA8NNNC, Package=0603, Tolerance=10%, Voltage=25V
C18 C19: library part "CAP CER 22pF 0805 50VDC 10% X5R", "CAP CER 22pF 0805 50VDC 10% X5R", Dielectric=X5R, Manufacturer="Samsung Electro-Mechanics", Manufacturer Part Number=CL10A106KP8NNNC, Package=0805, Tolerance=10%, Voltage=50V
C20 C21 C22: library part "CAP CER 10uF 1206 25VDC 10% TANTAL", "CAP CER 10uF 1206 16VDC 10% TANTAL", Dielectric=Tantalum, Manufacturer="Kyocera AVX", Manufacturer Part Number=TAJA106K016RNJ, Package=1206, Supplier Part Number 1=581-TAJA106K016R, Voltage=16V
C24: library part "CAP CER 10nF 0603 50VDC 10% X7R", "CAP CER 10nF 0603 50VDC 10% X7R", Dielectric=X7R, Manufacturer=YAGEO, Manufacturer Part Number=CC0603KRX7R9BB103, Tolerance=10%, Voltage=50V
D1: "Schottky Diodes & Rectifiers 50V 5A", If - Forward Current=5A, Manufacturer="Diodes Inc.", Package="SMC (DO-214AB)", Supplier Part Number 1=621-B550C-F, Vf - Forward Voltage=575mV, Vrrm - Repetitive Reverse Voltage=50V
FT1: "USB Interface IC USB to Serial UART Enhanced IC SSOP-28"
J1 J8 J11 J12: library part TERM_BLOCK_2PIN_VERT_3.5MM, "300V 8A 2 Straight pin -40?~+105? 1 3.5mm Green Board Edge/Receptacle-Close Plugin,P=3.5mm Pluggable System Terminal Block ROHS", Manufacturer=DIBO
J2 J3 J4 J5 J6: library part Header_1x4, "Male Header 1x4", Manufacturer="Ckmtw(Shenzhen Cankemeng)", Manufacturer Part Number=B-2100S04P-A110
J7: library part Header_2x3, "Male Header 2x3"
J9 J10: library part Header_1x6, "Female Header 1x6", Manufacturer=MOLEX, Manufacturer Part Number=0901471106, Supplier Part Number 1=538-90147-1106
LED1: library part LED_RED, "5mA 632nm Colorless transparence -40?~+85? 617.5nm~633.5nm Red 120° 60mW 0603 Light Emitting Diodes (LED) ROHS", Colour=Red, Forward Current=5mA, Manufacturer="Everlight Elec", Manufacturer Part Number=19-217/R6C-AL1M2VY/3T, Package=0603, Supplier Part Number 1=638-19217R6CAL1M2VY3
LED2: library part LED_GREEN, "20mA 518nm Colorless transparence -40?~+85? 520nm~535nm Emerald 120° 110mW 0603 Light Emitting Diodes (LED) ROHS", Colour="Brilliant Green", Forward Current=20mA, Manufacturer="Everlight Elec", Manufacturer Part Number=19-217/GHC-YR1S2/3T, Package=0603, Supplier Part Number=C72043, Supplier Part Number 1=638-19217GHCYR1S23T
Q1: "MOSFET, Power; N-Ch; VDSS 100V; RDS(ON) 44Milliohms; ID 33A; D2Pak; PD 130W; VGS +/-20", Package="D2PAK Infineon / IR"
R1 R4 R8 R9 R14 R15: library part "RES 100K 0603 100mW 0.1%", "RES 100K 0603 100mW 0.1%", Manufacturer=YAGEO, Manufacturer Part Number=RT0603BRD07100KL, Package=0603, Power Rating=100mW, Supplier Part Number 1=603-RT0603BRD07100KL, Tolerance=0.1%
R2 R10 R11 R22 R28: library part "RES 10K 0603 100mW 0.1%", "RES 10K 0603 100mW 0.1%", Manufacturer=YAGEO, Manufacturer Part Number=RT0603BRE0710KL, Package=0603, Power Rating=100mW, Supplier Part Number 1=603-RT0603BRE0710KL, Tolerance=0.1%
R3 R12 R13 R30: library part "RES 10K 0805 125mW 1%", "RES 10K 0805 125mW 1%", Manufacturer="UNI-ROYAL(Uniroyal Elec)", Manufacturer Part Number=0805W8F1002T5E, Package=0805, Power Rating=125mW, Supplier Part Number 1=303-0805W8F1002T5E, Tolerance=1%
R5 R6 R16 R17 R19 R20: library part "RES 0.1R TH", "RES 0.1R TH"
R7 R18 R21: "Potentiometer"
R23 R24: library part "RES 1K 0603 250mW 5%", "RES 100K 0603 250mW 5%", Manufacturer=Panasonic, Manufacturer Part Number=ERJ-PA3J102V, Package=0603, Power Rating=250mW, Supplier Part Number 1=667-ERJ-PA3J102V, Tolerance=5%
R25 R26: library part "RES 330R 0603 100mW 5%", "RES 330R 0603 100mW 5%", Manufacturer=Panasonic, Manufacturer Part Number=ERJ-3GEYJ331V, Package=0603, Power Rating=100mW, Supplier Part Number 1=667-ERJ-3GEYJ331V, Tolerance=5%
R27: library part "RES 4K7 0805 125mW 1%", "RES 4K7 0805 125mW 1%", Manufacturer="UNI-ROYAL(Uniroyal Elec)", Manufacturer Part Number=0805W8F4701T5E, Package=0805, Power Rating=125mW, Supplier Part Number 1=303-0805W8F4701T5E, Tolerance=1%
R29: library part "RES 5K1 0805 125mW 1%", "RES 5K1 0805 125mW 1%", Manufacturer="UNI-ROYAL(Uniroyal Elec)", Manufacturer Part Number=0805W8F4701T5E, Package=0805, Power Rating=125mW, Supplier Part Number 1=303-0805W8F4701T5E, Tolerance=1%
R31 R32 R33: library part "RES 470R 0603 250mW 1%", "RES 470R 0603 250mW 1%", Manufacturer=YAGEO, Manufacturer Part Number=ESR03EZPF4700, Package=0603, Power Rating=250mW, Supplier Part Number 1=755-ESR03EZPF4700, Tolerance=1%
S1 S2 S3: "DS05-127-2-04BK-SMT-TR", Package=None
T1 T2: "Trans GP BJT NPN 45V 0.1A 500mW 3-Pin TO-92 T/R", Package=None
USB: "USB - micro B USB 2.0 Receptacle Connector 5 Position Surface Mount, Right Angle; Through Hole", Package=None
Y1: "16 MHz ±10ppm Crystal 18pF 40 Ohms HC-49/US", Package=Package

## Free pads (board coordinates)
  round 3.2 hole 3.2 unplated: ""(31.5,102.625) ""(56.25,64) ""(120,119.5)

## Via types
v1: diameter 0.6, hole 0.3, Top Layer to Bottom Layer, 350 vias

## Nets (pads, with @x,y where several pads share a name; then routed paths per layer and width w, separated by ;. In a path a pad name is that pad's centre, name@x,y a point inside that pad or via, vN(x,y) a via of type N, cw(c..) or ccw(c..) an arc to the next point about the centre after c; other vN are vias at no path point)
ADC6: IC1.19 J9.4 | length 28.9
  Top Layer w0.3: IC1.19@95.139,109.692 97,111.553 97,114.207 99.793,117 102.5,117 104.5,119 113,119 115.04,121.04 J9.4@115.04,123.75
